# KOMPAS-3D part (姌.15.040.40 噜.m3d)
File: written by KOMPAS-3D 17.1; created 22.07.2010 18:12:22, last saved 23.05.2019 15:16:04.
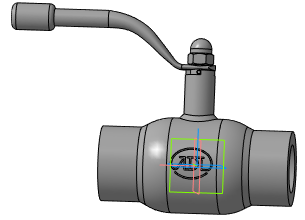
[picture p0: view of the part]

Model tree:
1. Плоскость XY
2. Плоскость ZX
3. Плоскость ZY
4. Ось X
5. Ось Y
6. Ось Z
7. Начало координат
8. Операция без истории:3  (labels: Сталь 20  ГОСТ 1050-88)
